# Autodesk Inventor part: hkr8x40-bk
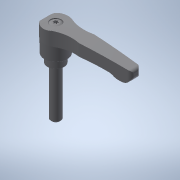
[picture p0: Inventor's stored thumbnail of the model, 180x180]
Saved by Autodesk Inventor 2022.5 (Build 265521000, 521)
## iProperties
Created: 2017-09
Part Number: hkr8x40-bk
Material: 一般
Document SubType Name: Modeling
Designer: imaocorp
Density: 1 g/cm^3
Appearance: 既定
Author: imaocorp
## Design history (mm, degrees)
node "hkr8x40-bk.x_t1"
node "hkr8x40-bk"
node "Base1"
